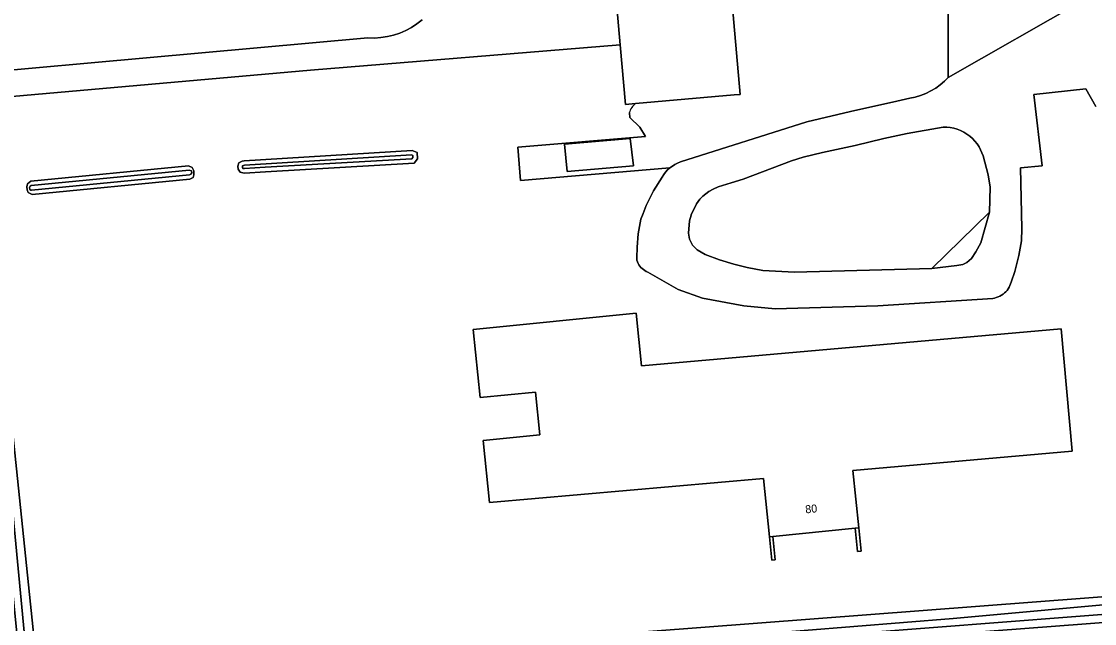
# Model space of a CAD drawing. Extents: x 158132 to 159664, y 385256 to 387218.
# Drawn here: x 158558.9 to 158692.9, y 386531.1 to 386606.3 of the extents above; entities that cross this region are included whole.
import ezdxf

# ---------------------------------------------------------------- set-up
doc = ezdxf.new("R2010")
doc.units = 0
for name, color, linetype in [('IMGEO_Berm_gesloten', 7, 'Continuous'), ('IMGEO_Gemengd_bos', 7, 'Continuous'), ('IMGEO_Groenvoorziening', 7, 'Continuous'), ('IMGEO_Muur', 7, 'Continuous'), ('IMGEO_Oever', 7, 'Continuous'), ('IMGEO_Pand', 7, 'Continuous'), ('IMGEO_Pand_nummerreeks', 7, 'Continuous'), ('IMGEO_Rijbaan_lokaal_gesloten', 7, 'Continuous'), ('IMGEO_Voetpad_open', 7, 'Continuous'), ('IMGEO_Waterloop', 7, 'Continuous')]:
    doc.layers.add(name, color=color, linetype=linetype)

msp = doc.modelspace()

# ---------------------------------------------------------------- linework, layer by layer
at = {"layer": 'IMGEO_Berm_gesloten'}
msp.add_lwpolyline([(158679.78, 386582.49), (158672.56, 386575.46), (158675.69, 386575.84), (158676.44, 386575.97), (158676.94, 386576.23), (158677.52, 386576.73), (158678.06, 386577.56), (158678.68, 386578.69)], close=True, dxfattribs=at)
at = {"layer": 'IMGEO_Gemengd_bos'}
msp.add_lwpolyline([(158710.5, 386585.82), (158694.75, 386594.73), (158699.27, 386534.87), (158699.52, 386531.69), (158557.25, 386520.85), (158552.81, 386577.12)], dxfattribs=at)
at = {"layer": 'IMGEO_Groenvoorziening'}
for points in [[(158525.58, 386597.37), (158602.14, 386604.25), (158602.95, 386604.24), (158603.76, 386604.29), (158604.56, 386604.42), (158605.35, 386604.61), (158606.11, 386604.86), (158606.86, 386605.18), (158607.57, 386605.57), (158608.25, 386606.01), (158608.89, 386606.5)], [(158635.57, 386596.07), (158634.29, 386595.96), (158633.64, 386603.39), (158594.96, 386600.25), (158554.82, 386596.68)], [(158693.04, 386595.68), (158691.82, 386597.92), (158685.29, 386597.2), (158686.37, 386588.28), (158683.66, 386588.02), (158683.81, 386580.47), (158683.75, 386578.93), (158683.45, 386577.09), (158682.94, 386575.1), (158682.48, 386573.78), (158682.41, 386573.56), (158682.32, 386573.34), (158682.22, 386573.13), (158682.1, 386572.93), (158681.96, 386572.74), (158681.8, 386572.57), (158681.64, 386572.41), (158681.46, 386572.26), (158681.26, 386572.13), (158681.06, 386572.01), (158680.84, 386571.91), (158680.62, 386571.84), (158680.4, 386571.78), (158680.17, 386571.74), (158665.83, 386570.82), (158653, 386570.44), (158649.07, 386570.81), (158643.94, 386571.76), (158640.88, 386572.86), (158637.09, 386575.02), (158636.9, 386575.1), (158636.72, 386575.21), (158636.55, 386575.33), (158636.39, 386575.46), (158636.24, 386575.6), (158636.11, 386575.76), (158635.98, 386575.93), (158635.88, 386576.11), (158635.79, 386576.3), (158635.71, 386576.49), (158635.71, 386576.8), (158635.75, 386578.11), (158635.89, 386579.81), (158636.22, 386581.63), (158636.51, 386582.34), (158636.91, 386583.34), (158637.81, 386585.15), (158638.87, 386586.88), (158639.08, 386587.2), (158639.31, 386587.49), (158639.57, 386587.77), (158639.85, 386588.02), (158621.18, 386586.47), (158620.84, 386590.63), (158636.81, 386591.96), (158636.09, 386593.13), (158634.85, 386594.34), (158634.79, 386594.91)], [(158555.4, 386577.39), (158560.93, 386524.32), (158699.27, 386534.87), (158694.75, 386594.73)]]:
    msp.add_lwpolyline(points, dxfattribs=at)
for points in [[(158679.84, 386585.61), (158679.61, 386587.16), (158678.98, 386589.54), (158678.47, 386590.65), (158678.22, 386591.02), (158677.94, 386591.37), (158677.64, 386591.69), (158677.3, 386591.99), (158676.94, 386592.25), (158676.56, 386592.49), (158676.16, 386592.68), (158675.74, 386592.85), (158675.32, 386592.98), (158674.88, 386593.06), (158674.44, 386593.11), (158673.99, 386593.12), (158669.49, 386592.33), (158666.59, 386591.69), (158662.99, 386590.84), (158658.92, 386589.95), (158656.52, 386589.36), (158655.04, 386588.9), (158648.99, 386586.62), (158647.5, 386586.15), (158645.9, 386585.66), (158645.27, 386585.37), (158644.7, 386585.07), (158643.98, 386584.49), (158643.6, 386584.11), (158643.18, 386583.53), (158642.78, 386582.67), (158642.53, 386582.19), (158642.51, 386582.14), (158642.32, 386581.4), (158642.17, 386579.88), (158642.31, 386579.11), (158642.66, 386578.38), (158643.25, 386577.79), (158644.24, 386577.2), (158646.03, 386576.55), (158647.83, 386576.02), (158649.5, 386575.6), (158651.48, 386575.2), (158655.4, 386575.02), (158672.56, 386575.46), (158679.78, 386582.49)], [(158607.66, 386590.22), (158608.28, 386589.96), (158608.33, 386589.15), (158607.91, 386588.6), (158589.36, 386587.55), (158586.73, 386587.38), (158586.53, 386587.4), (158586.16, 386587.49), (158585.92, 386587.89), (158585.89, 386588.23), (158586.02, 386588.66), (158586.44, 386588.88), (158586.67, 386588.91)], [(158580.19, 386588.08), (158580.38, 386587.66), (158580.41, 386587.15), (158580.32, 386586.83), (158579.9, 386586.62), (158560.18, 386584.71), (158559.7, 386584.96), (158559.57, 386585.28), (158559.53, 386585.67), (158559.61, 386586.05), (158560.02, 386586.36), (158579.74, 386588.27)], [(158688.73, 386567.95), (158690.08, 386552.65), (158662.71, 386550.23), (158663.44, 386543.07), (158663.73, 386540.19), (158663.3, 386540.14), (158663.01, 386543.03), (158652.72, 386541.99), (158653.02, 386539.1), (158652.59, 386539.06), (158652.3, 386541.95), (158651.56, 386549.25), (158617.33, 386546.23), (158616.55, 386553.98), (158623.61, 386554.69), (158623.07, 386560.04), (158616.14, 386559.34), (158615.28, 386567.83), (158635.64, 386569.9), (158636.3, 386563.33)]]:
    msp.add_lwpolyline(points, close=True, dxfattribs=at)
msp.add_arc((158636.97, 386594.28), 2.28, 128.0684, 163.7552, dxfattribs=at)
at = {"layer": 'IMGEO_Muur'}
for points in [[(158663.44, 386543.07), (158663.01, 386543.03), (158663.3, 386540.14), (158663.73, 386540.19)], [(158652.72, 386541.99), (158652.3, 386541.95), (158652.59, 386539.06), (158653.02, 386539.1)]]:
    msp.add_lwpolyline(points, close=True, dxfattribs=at)
at = {"layer": 'IMGEO_Oever'}
for points in [[(158586.73, 386587.38), (158589.36, 386587.55), (158607.91, 386588.6), (158608.33, 386589.15), (158608.28, 386589.96), (158607.66, 386590.22), (158586.67, 386588.91), (158586.44, 386588.88), (158586.02, 386588.66), (158585.89, 386588.23), (158585.92, 386587.89), (158586.16, 386587.49), (158586.53, 386587.4)], [(158586.73, 386587.94), (158586.62, 386587.95), (158586.52, 386587.97), (158586.46, 386588.07), (158586.45, 386588.18), (158586.48, 386588.27), (158586.61, 386588.34), (158586.72, 386588.35), (158607.57, 386589.66), (158607.74, 386589.58), (158607.76, 386589.32), (158607.62, 386589.14), (158589.32, 386588.11)], [(158560.18, 386584.71), (158579.9, 386586.62), (158580.32, 386586.83), (158580.41, 386587.15), (158580.38, 386587.66), (158580.19, 386588.08), (158579.74, 386588.27), (158560.02, 386586.36), (158559.61, 386586.05), (158559.53, 386585.67), (158559.57, 386585.28), (158559.7, 386584.96)], [(158560.13, 386585.23), (158560.04, 386585.24), (158559.91, 386585.35), (158559.88, 386585.56), (158559.93, 386585.73), (158560.08, 386585.83), (158579.79, 386587.74), (158580.08, 386587.67), (158580.13, 386587.43), (158580.03, 386587.25), (158579.85, 386587.15)], [(158699.52, 386531.69), (158699.27, 386534.87), (158560.93, 386524.32), (158555.4, 386577.39), (158554.97, 386582.61), (158552.53, 386582.41), (158552.39, 386582.4), (158552.81, 386577.12), (158557.25, 386520.85)], [(158553.1, 386581.98), (158554.24, 386582.06), (158554.54, 386578.89), (158559.85, 386523.08), (158621.58, 386527.43), (158638, 386528.76), (158675.25, 386531.75), (158698.53, 386533.91), (158698.65, 386532.63), (158664.15, 386529.97), (158634.37, 386527.66), (158583.72, 386523.55), (158559.05, 386521.76), (158558.32, 386529.53), (158553.17, 386581.3)]]:
    msp.add_lwpolyline(points, close=True, dxfattribs=at)
at = {"layer": 'IMGEO_Pand'}
for points in [[(158644.57, 386643.58), (158631.02, 386642.4), (158630.24, 386642.33), (158633.64, 386603.39), (158634.29, 386595.96), (158635.57, 386596.07), (158647.89, 386597.14), (158648.61, 386597.21)], [(158627.04, 386587.57), (158635.32, 386588.29), (158634.89, 386591.71), (158626.7, 386591)], [(158690.08, 386552.65), (158688.73, 386567.95), (158636.3, 386563.33), (158635.64, 386569.9), (158615.28, 386567.83), (158616.14, 386559.34), (158623.07, 386560.04), (158623.61, 386554.69), (158616.55, 386553.98), (158617.33, 386546.23), (158651.56, 386549.25), (158652.3, 386541.95), (158652.72, 386541.99), (158663.01, 386543.03), (158663.44, 386543.07), (158662.71, 386550.23)]]:
    msp.add_lwpolyline(points, close=True, dxfattribs=at)
at = {"layer": 'IMGEO_Rijbaan_lokaal_gesloten'}
for points in [[(158554.82, 386596.68), (158594.96, 386600.25), (158633.64, 386603.39), (158630.24, 386642.33)], [(158691.56, 386608.98), (158674.62, 386599.33), (158674.14, 386598.87), (158673.61, 386598.41), (158673.05, 386598), (158672.45, 386597.63), (158671.82, 386597.32), (158671.17, 386597.06), (158670.5, 386596.87), (158669.81, 386596.73), (158668.21, 386596.35), (158662.4, 386595.08), (158656.97, 386593.78), (158641.16, 386588.77), (158640.81, 386588.62), (158640.48, 386588.45), (158640.16, 386588.25), (158639.85, 386588.02), (158639.57, 386587.77), (158639.31, 386587.49), (158639.08, 386587.2), (158638.87, 386586.88), (158637.81, 386585.15), (158636.91, 386583.34), (158636.51, 386582.34), (158636.22, 386581.63), (158635.89, 386579.81), (158635.75, 386578.11), (158635.71, 386576.8), (158635.71, 386576.49), (158635.79, 386576.3), (158635.88, 386576.11), (158635.98, 386575.93), (158636.11, 386575.76), (158636.24, 386575.6), (158636.39, 386575.46), (158636.55, 386575.33), (158636.72, 386575.21), (158636.9, 386575.1), (158637.09, 386575.02), (158640.88, 386572.86), (158643.94, 386571.76), (158649.07, 386570.81), (158653, 386570.44), (158665.83, 386570.82), (158680.17, 386571.74), (158680.4, 386571.78), (158680.62, 386571.84), (158680.84, 386571.91), (158681.06, 386572.01), (158681.26, 386572.13), (158681.46, 386572.26), (158681.64, 386572.41), (158681.8, 386572.57), (158681.96, 386572.74), (158682.1, 386572.93), (158682.22, 386573.13), (158682.32, 386573.34), (158682.41, 386573.56), (158682.48, 386573.78), (158682.94, 386575.1), (158683.45, 386577.09), (158683.75, 386578.93), (158683.81, 386580.47), (158683.66, 386588.02), (158686.37, 386588.28), (158685.29, 386597.2), (158691.82, 386597.92), (158693.04, 386595.68)], [(158674.59, 386608.22), (158674.62, 386599.33), (158691.56, 386608.98)], [(158608.89, 386606.5), (158608.25, 386606.01), (158607.57, 386605.57), (158606.86, 386605.18), (158606.11, 386604.86), (158605.35, 386604.61), (158604.56, 386604.42), (158603.76, 386604.29), (158602.95, 386604.24), (158602.14, 386604.25), (158525.58, 386597.37)]]:
    msp.add_lwpolyline(points, dxfattribs=at)
msp.add_lwpolyline([(158679.78, 386582.49), (158678.68, 386578.69), (158678.06, 386577.56), (158677.52, 386576.73), (158676.94, 386576.23), (158676.44, 386575.97), (158675.69, 386575.84), (158672.56, 386575.46), (158655.4, 386575.02), (158651.48, 386575.2), (158649.5, 386575.6), (158647.83, 386576.02), (158646.03, 386576.55), (158644.24, 386577.2), (158643.25, 386577.79), (158642.66, 386578.38), (158642.31, 386579.11), (158642.17, 386579.88), (158642.32, 386581.4), (158642.51, 386582.14), (158642.53, 386582.19), (158642.78, 386582.67), (158643.18, 386583.53), (158643.6, 386584.11), (158643.98, 386584.49), (158644.7, 386585.07), (158645.27, 386585.37), (158645.9, 386585.66), (158647.5, 386586.15), (158648.99, 386586.62), (158655.04, 386588.9), (158656.52, 386589.36), (158658.92, 386589.95), (158662.99, 386590.84), (158666.59, 386591.69), (158669.49, 386592.33), (158673.99, 386593.12), (158674.44, 386593.11), (158674.88, 386593.06), (158675.32, 386592.98), (158675.74, 386592.85), (158676.16, 386592.68), (158676.56, 386592.49), (158676.94, 386592.25), (158677.3, 386591.99), (158677.64, 386591.69), (158677.94, 386591.37), (158678.22, 386591.02), (158678.47, 386590.65), (158678.98, 386589.54), (158679.61, 386587.16), (158679.84, 386585.61)], close=True, dxfattribs=at)
at = {"layer": 'IMGEO_Voetpad_open'}
for points in [[(158644.57, 386643.58), (158648.61, 386597.21), (158647.89, 386597.14), (158635.57, 386596.07)], [(158662.4, 386595.08), (158668.21, 386596.35), (158669.81, 386596.73), (158670.5, 386596.87), (158671.17, 386597.06), (158671.82, 386597.32), (158672.45, 386597.63), (158673.05, 386598), (158673.61, 386598.41), (158674.14, 386598.87), (158674.62, 386599.33), (158674.59, 386608.22)], [(158634.79, 386594.91), (158634.85, 386594.34), (158636.09, 386593.13), (158636.81, 386591.96), (158620.84, 386590.63), (158621.18, 386586.47), (158639.85, 386588.02), (158640.16, 386588.25), (158640.48, 386588.45), (158640.81, 386588.62), (158641.16, 386588.77), (158656.97, 386593.78), (158662.4, 386595.08)]]:
    msp.add_lwpolyline(points, dxfattribs=at)
msp.add_lwpolyline([(158635.32, 386588.29), (158627.04, 386587.57), (158626.7, 386591), (158634.89, 386591.71)], close=True, dxfattribs=at)
msp.add_arc((158636.97, 386594.28), 2.28, 128.0684, 163.7552, dxfattribs=at)
at = {"layer": 'IMGEO_Waterloop'}
for points in [[(158586.73, 386587.94), (158589.32, 386588.11), (158607.62, 386589.14), (158607.76, 386589.32), (158607.74, 386589.58), (158607.57, 386589.66), (158586.72, 386588.35), (158586.61, 386588.34), (158586.48, 386588.27), (158586.45, 386588.18), (158586.46, 386588.07), (158586.52, 386587.97), (158586.62, 386587.95)], [(158560.13, 386585.23), (158579.85, 386587.15), (158580.03, 386587.25), (158580.13, 386587.43), (158580.08, 386587.67), (158579.79, 386587.74), (158560.08, 386585.83), (158559.93, 386585.73), (158559.88, 386585.56), (158559.91, 386585.35), (158560.04, 386585.24)], [(158553.1, 386581.98), (158553.17, 386581.3), (158558.32, 386529.53), (158559.05, 386521.76), (158583.72, 386523.55), (158634.37, 386527.66), (158664.15, 386529.97), (158698.65, 386532.63), (158698.53, 386533.91), (158675.25, 386531.75), (158638, 386528.76), (158621.58, 386527.43), (158559.85, 386523.08), (158554.54, 386578.89), (158554.24, 386582.06)]]:
    msp.add_lwpolyline(points, close=True, dxfattribs=at)

# ---------------------------------------------------------------- texts
at = {"layer": 'IMGEO_Pand_nummerreeks'}
msp.add_text('80', height=1, rotation=5.5176, dxfattribs=at).set_placement((158656.81, 386544.89))

doc.saveas('drawing.dxf')
